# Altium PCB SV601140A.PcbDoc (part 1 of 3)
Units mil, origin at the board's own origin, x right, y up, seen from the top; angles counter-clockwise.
Board outline 5208 x 5464 mil, 4 copper layers (Top Layer, MidLayer1, MidLayer2, Bottom Layer), stack 61.2 mil thick; 45 components, 23 nets, 134 pads, 62 vias.
Unrouted connection lines stored in the file: 1.
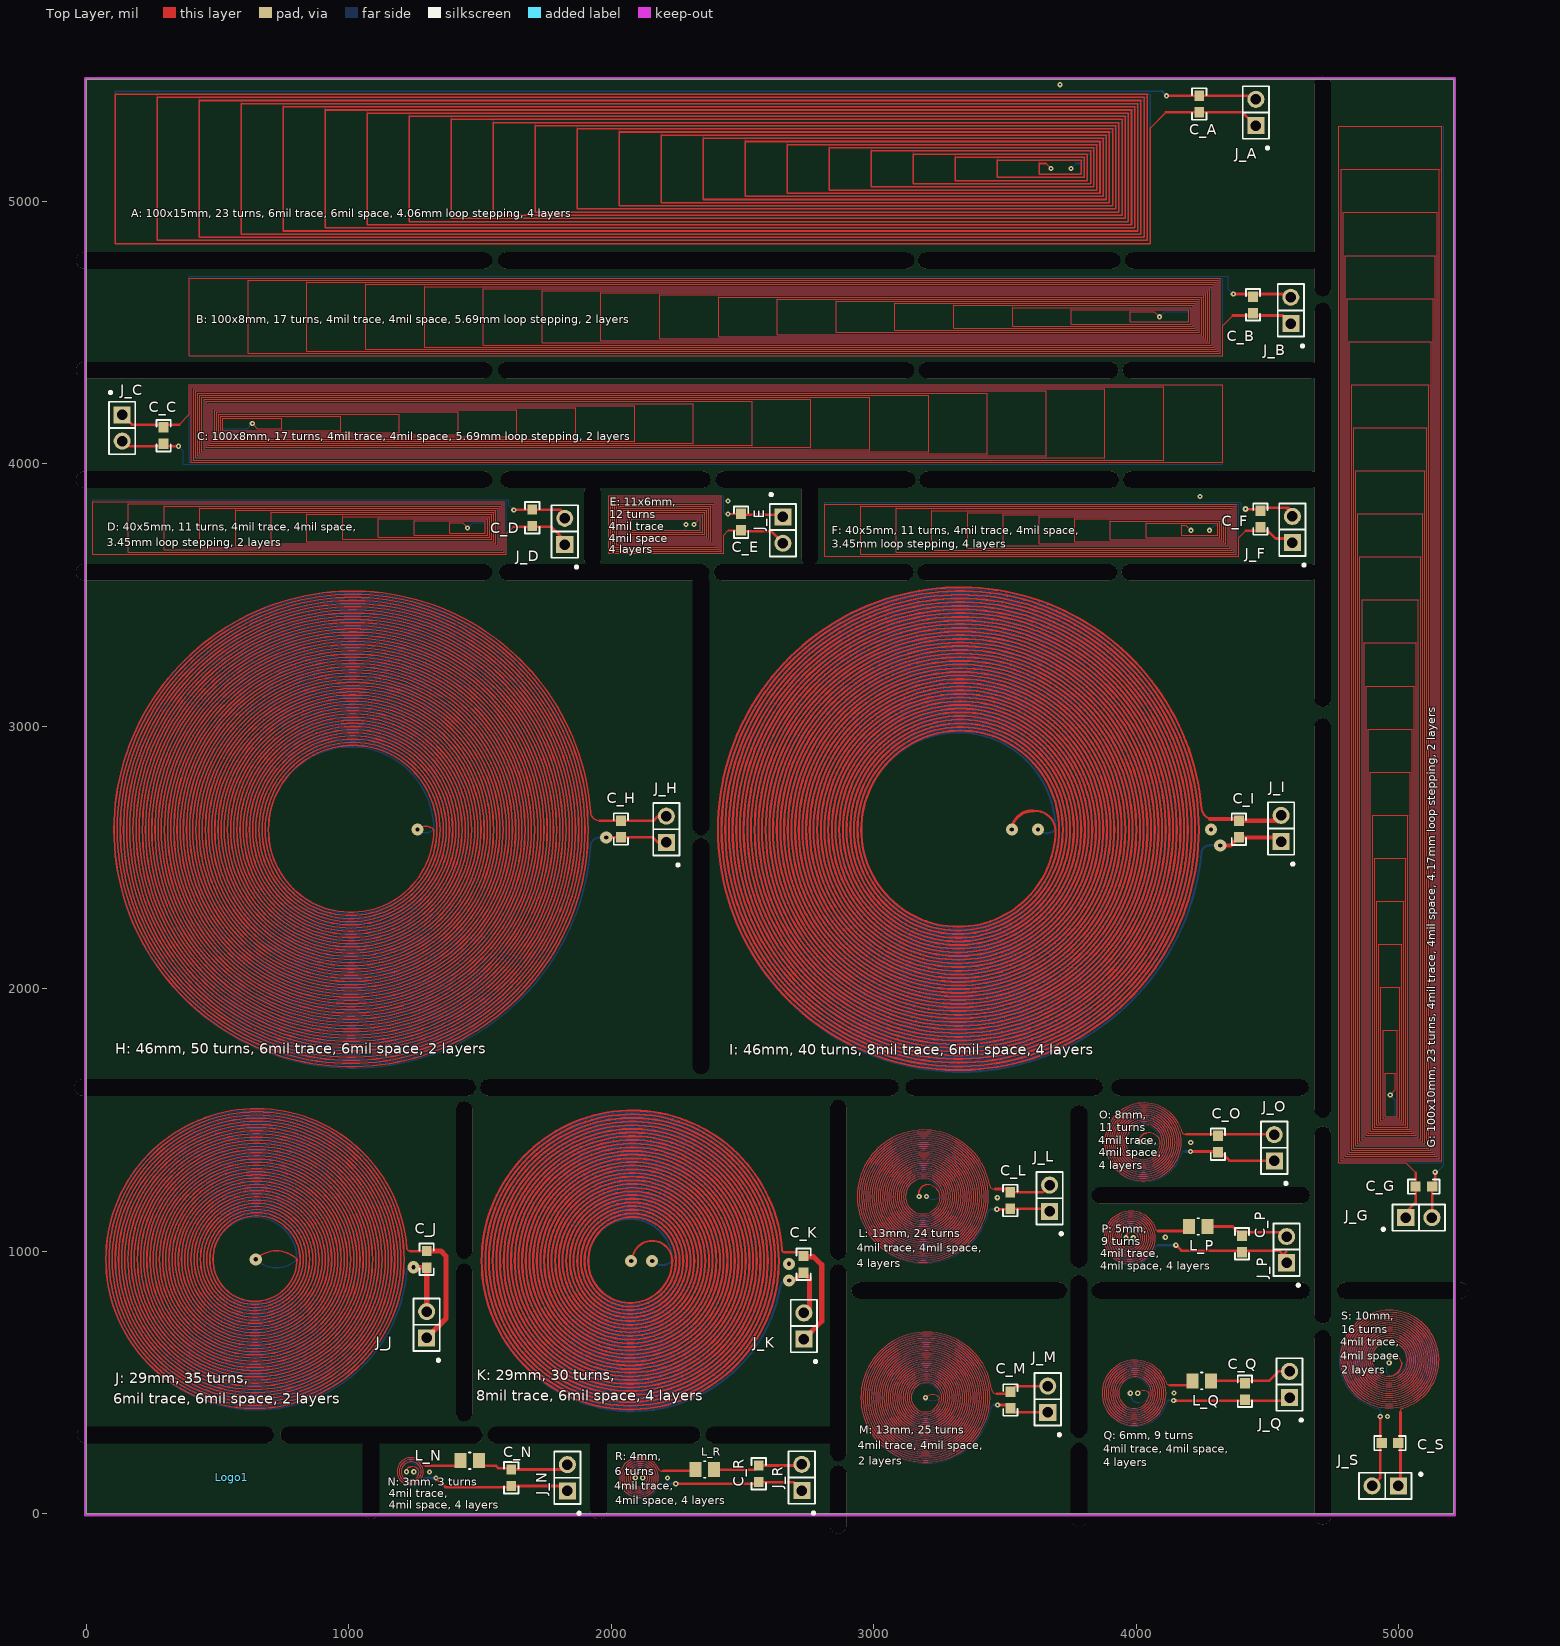
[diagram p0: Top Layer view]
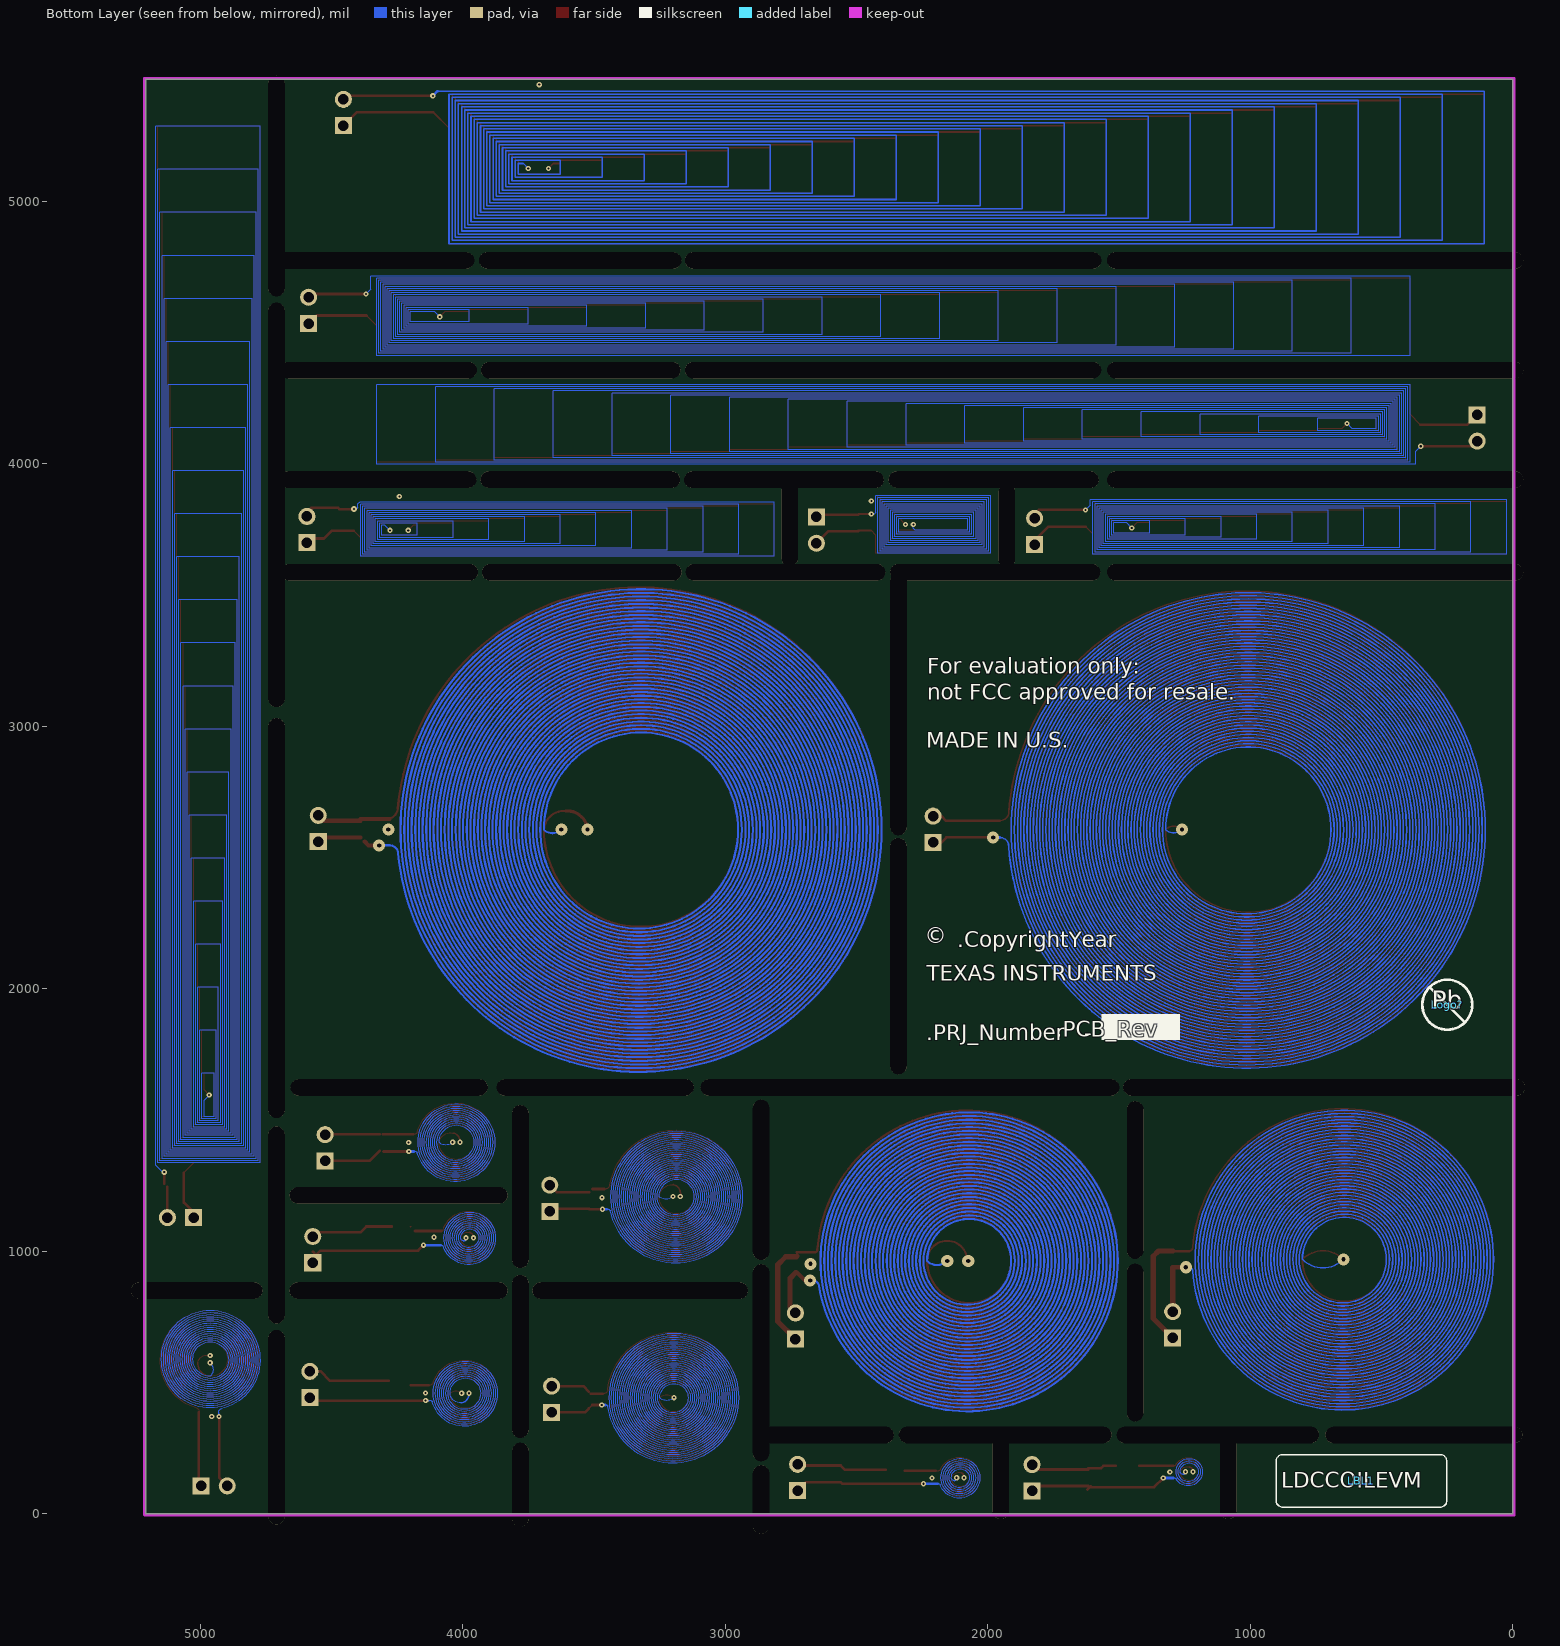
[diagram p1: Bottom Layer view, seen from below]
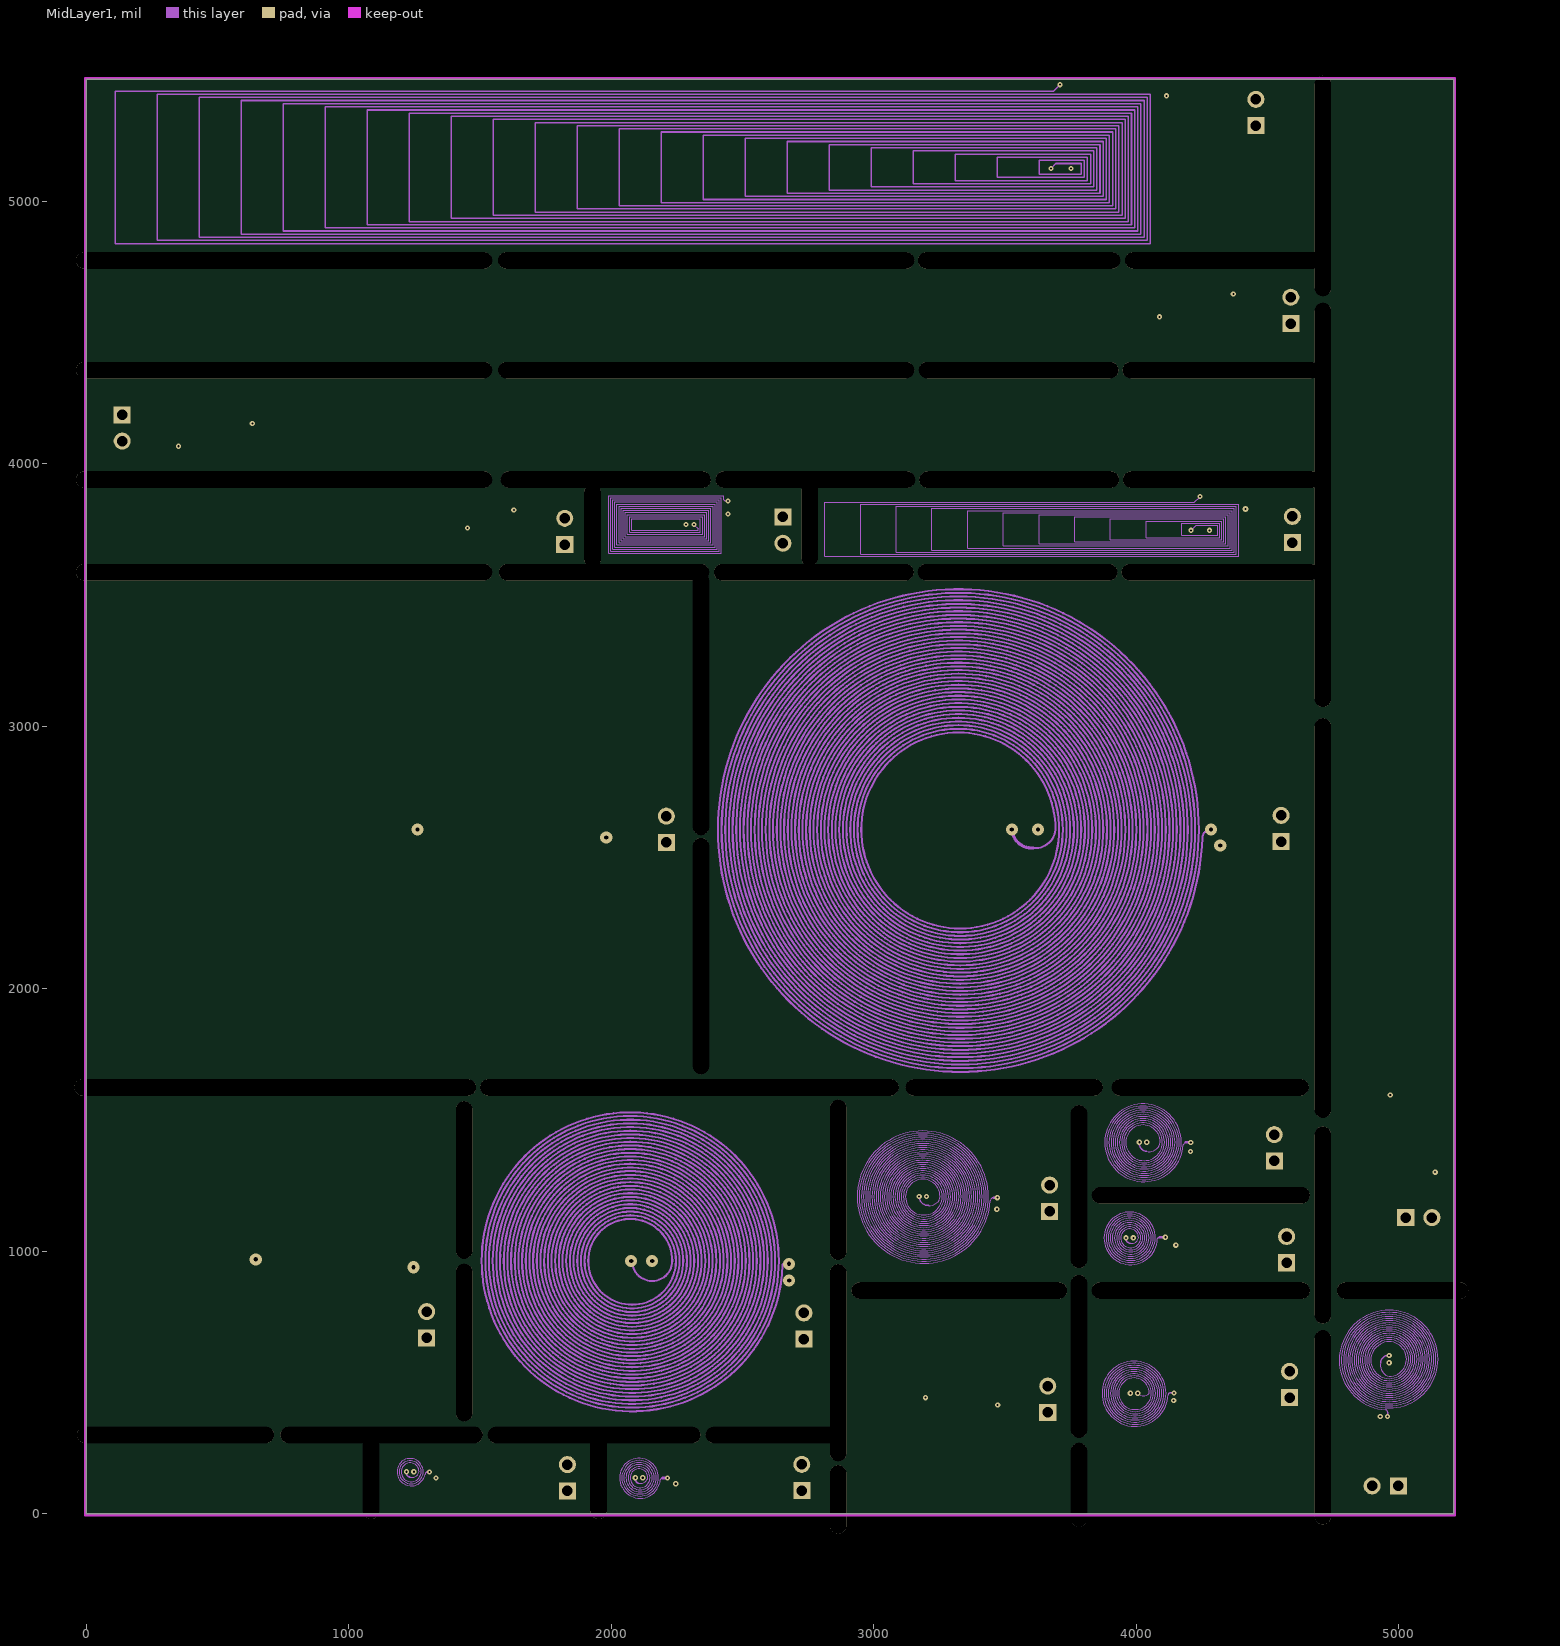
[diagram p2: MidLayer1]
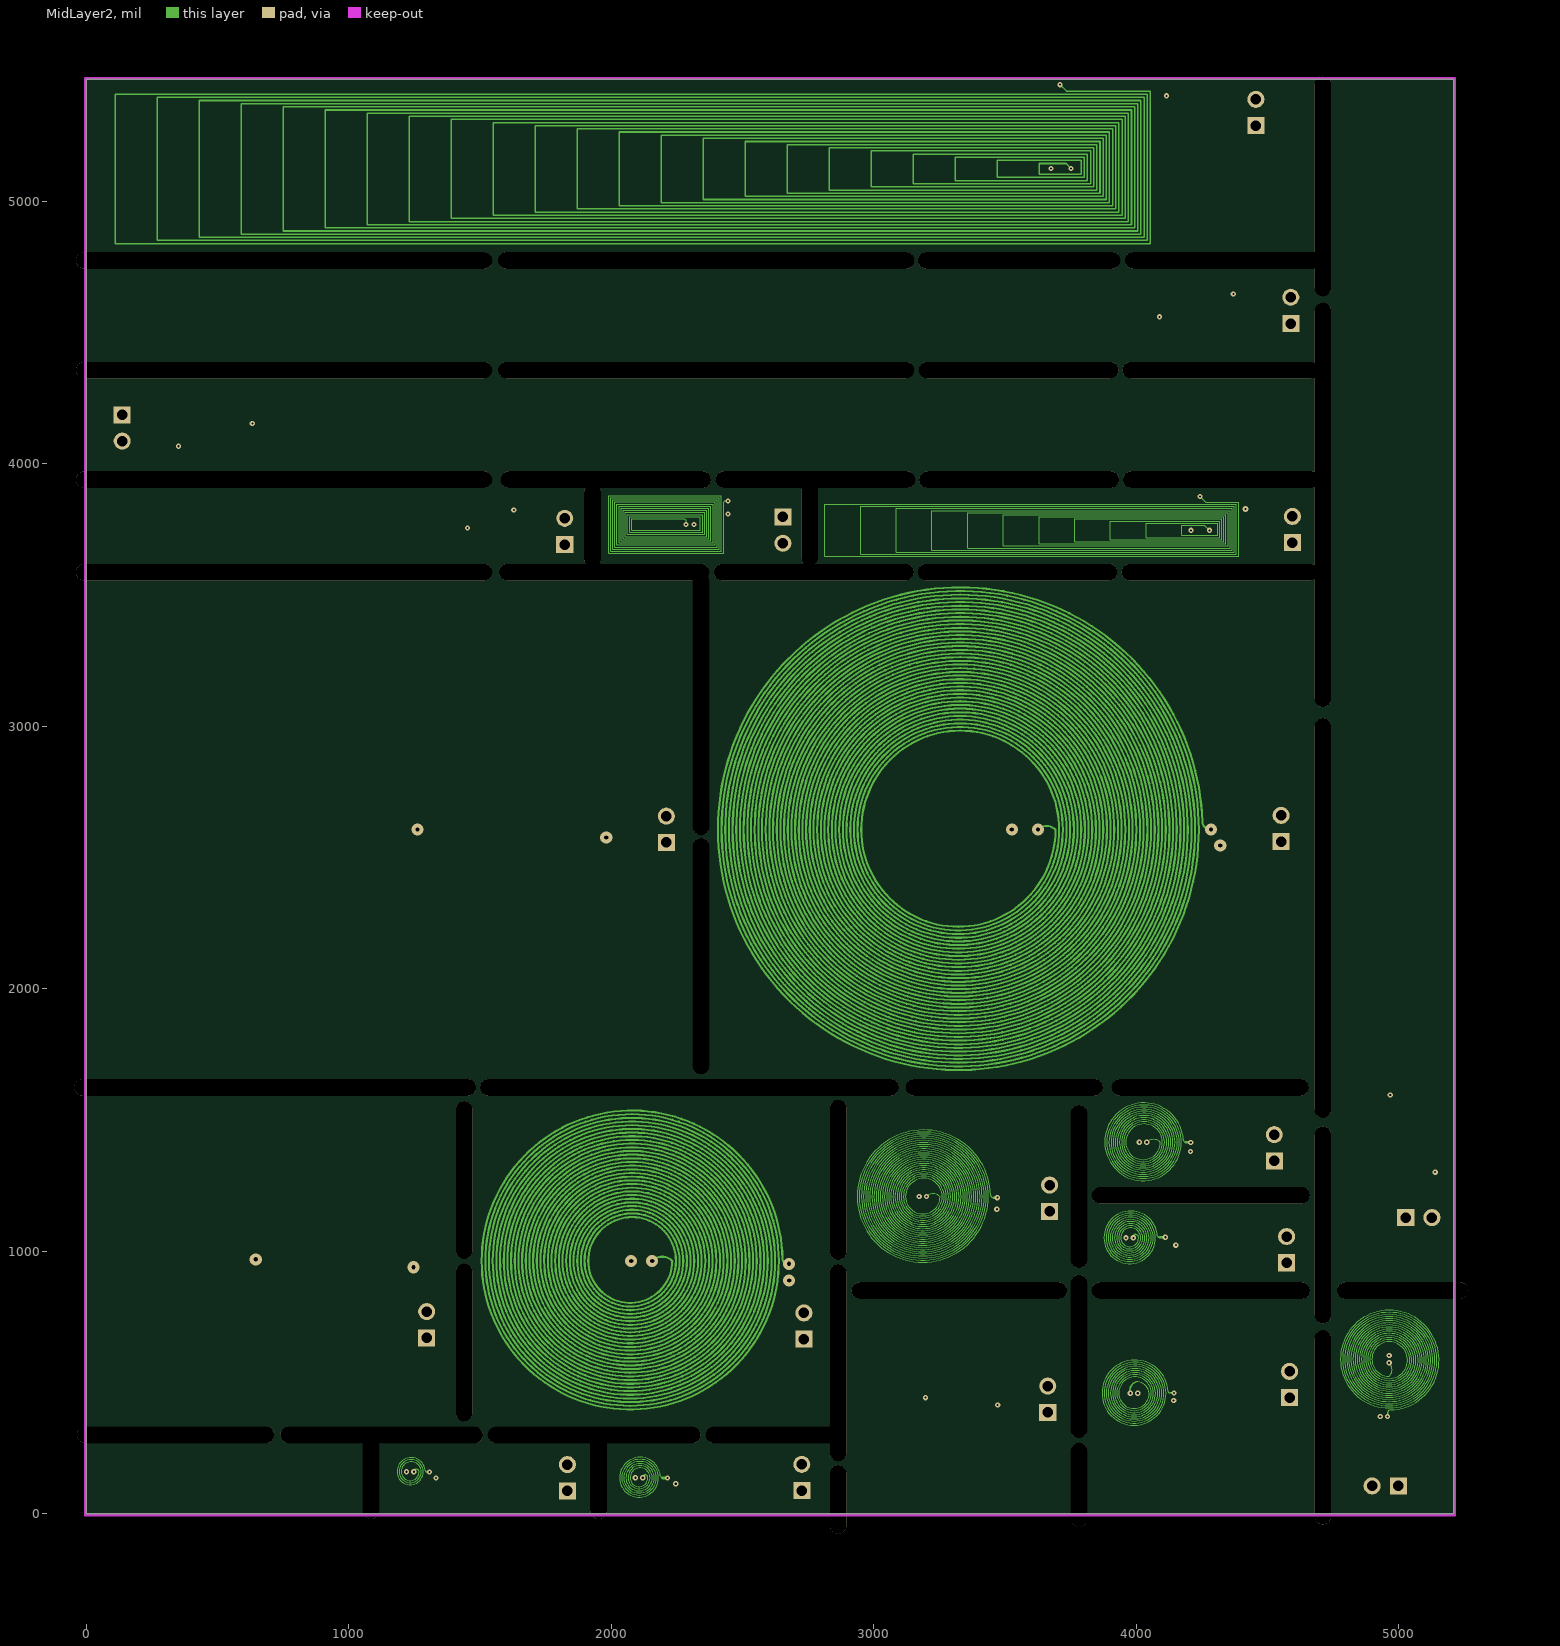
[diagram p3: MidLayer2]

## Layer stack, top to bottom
Top Solder: solder mask 0.4, Solder Resist, Dk 3.5
Top Layer: signal copper 1.4
Dielectric1: core 12.6, FR-4, Dk 3.9
MidLayer1: signal copper 1.4
Dielectric2: prepreg 30.4, FR-4, Dk 3.9
MidLayer2: signal copper 1.4
Dielectric3: core 12.6, FR-4, Dk 3.9
Bottom Layer: signal copper 1.4
Bottom Solder: solder mask 0.4, Solder Resist, Dk 3.5

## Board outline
0,0 0,5464 5208,5464 5208,0

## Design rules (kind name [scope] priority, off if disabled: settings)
AcuteAngle [All] p1: minimum=4.50000000000000E+0001 checktracksonly=FALSE
AssemblyTestPointUsage [All] p1: valid=2
Clearance Clearance_BoardEdge_MountingHoles [OnCopper and InComponentClass('Mounting Holes') vs IsKeepOut] p1: gap=40
Clearance Clearance_BoardEdge_Poly [OnCopper and InPoly vs IsKeepOut] p2: gap=25
Clearance Clearance_BoardEdge [OnCopper and Not InComponentClass('Logo') and not InComponentClass('FiducialMark') and not InRegion(1000,500,4000,800) and Not IsKeepout vs IsKeepOut] p3: gap=20
Clearance Clearance_Poly [InPolygon] p4: gap=25
Clearance [All] p5: gap=4
ComponentClearance ComponentClearance_Logo [InComponentClass('Logo')] p1: gap=50 collisioncheckmode=3 verticalgap=10 showdistances=FALSE
ComponentClearance ComponentClearance_ScrewToNut [(HasFootprint('NY PMS 440 0025 PH')) vs (HasFootprint('Keystone_1902C'))] p2: gap=5 collisioncheckmode=3 verticalgap=10 showdistances=FALSE
ComponentClearance ComponentClearance_MountingHoles [InComponentClass('Mounting Holes')] p3: gap=250 collisioncheckmode=3 verticalgap=100000 showdistances=FALSE
ComponentClearance ComponentClearance_SmallPassives [HasFootprint('0201*') or HasFootprint('0402*') or HasFootprint('0508') or HasFootprint('0603*') or HasFootprint('0612') or HasFootprint('0805*') or HasFootprint('0815*') or HasFootprint('0830*') or HasFootprint('1206*') or HasFootprint('1210*') or HasFootprint('1808*') or HasFootprint('1812*') or HasFootprint('1825*') or HasFootprint('2010*') or HasFootprint('2220*') or HasFootprint('2225*') or HasFootprint('2512*') or HasFootprint('2728*') or HasFootprint('3518*') vs HasFootprint('0201*') or HasFootprint('0402*') or HasFootprint('0508') or HasFootprint('0603*') or HasFootprint('0612') or HasFootprint('0805*') or HasFootprint('0815*') or HasFootprint('0830*') or HasFootprint('1206*') or HasFootprint('1210*') or HasFootprint('1808*') or HasFootprint('1812*') or HasFootprint('1825*') or HasFootprint('2010*') or HasFootprint('2220*') or HasFootprint('2225*') or HasFootprint('2512*') or HasFootprint('2728*') or HasFootprint('3518*')] p4: gap=20 collisioncheckmode=3 verticalgap=10 showdistances=FALSE
ComponentClearance ComponentClearance_THtoSMT [IsThruComponent vs IsSMTComponent] p5: gap=100 collisioncheckmode=3 verticalgap=30 showdistances=FALSE
ComponentClearance ComponentClearance_THtoTH [IsThruComponent vs IsThruComponent] p6: gap=118.11 collisioncheckmode=3 verticalgap=30 showdistances=FALSE
ComponentClearance [All] p7: gap=40 collisioncheckmode=3 verticalgap=10 showdistances=FALSE
DiffPairsRouting [All] p1: maxlimit=100 minlimit=10 mostfreqgap=10 toplayer_minwidth=15 toplayer_maxwidth=15 toplayer_prefwidth=15 midlayer1_minwidth=15 midlayer1_maxwidth=15 midlayer1_prefwidth=15 midlayer2_minwidth=15 midlayer2_maxwidth=15 midlayer2_prefwidth=15 bottomlayer_minwidth=15 bottomlayer_maxwidth=15 bottomlayer_prefwidth=15 maxuncoupledlength=1000
FabricationTestPointUsage TestPointUsage [All] p1: valid=2 allowmultiple=FALSE
FabricationTestpoint Testpoint [All] p1: side=3 testpointundercomponent=TRUE minsize=40 maxsize=100 preferedsize=60 minholesize=0 maxholesize=40 preferedholesize=32 testpointgrid=1 allowsidetop=TRUE allowsidebottom=TRUE usegrid=TRUE gridtolerance=0.01
FanoutControl Fanout_LCC [IsLCC] p1: bgadir=Out bgaviamode=Centered fanoutstyle=Auto fanoutdirection=Alternating viagrid=1 // Fanout_LCC (Default Rule)
FanoutControl Fanout_BGA [IsBGA] p2: bgadir=Out bgaviamode=Centered fanoutstyle=Auto fanoutdirection=Alternating viagrid=1 // Fanout_BGA (Default Rule)
FanoutControl Fanout_Default [All] p4: bgadir=Out bgaviamode=Centered fanoutstyle=Auto fanoutdirection=Alternating viagrid=1 // Fanout_Default (Default Rule)
FanoutControl Fanout_Small [(CompPinCount < 5)] p5: bgadir=Out bgaviamode=Centered fanoutstyle=Auto fanoutdirection=OutThenIn viagrid=1 // Fanout_Small (Default Rule)
HoleSize [All] p1: absolutevalues=TRUE maxlimit=251 minlimit=8 maxpercent=80.000 minpercent=20.000
MinimumAnnularRing MinimumAnnularRing_ThermalPadVias [IsVia and InAnyComponent] p1: minimumring=5.91
MinimumAnnularRing [All] p2: minimumring=6
MinimumSolderMaskSliver MinimumSolderMaskSliver_Logo [InComponentClass('Logo') vs InComponentClass('Logo')] p1: minsoldermaskwidth=0.7
MinimumSolderMaskSliver [All] p2: minsoldermaskwidth=3.94
PlaneConnect [All] p1: planeconnectstyle=Relief reliefexpansion=10 reliefentries=4 reliefconductorwidth=10 reliefairgap=10
PolygonConnect [All] p1: connectstyle=Relief reliefconductorwidth=10 reliefentries=4 polygonreliefangle="90 Angle" airgapwidth=10
RoutingVias ThermalPadVias [IsVia and InAnyComponent] p1: holewidth=7.87 width=19.68 viastyle="Through Hole" minholewidth=7.87 minwidth=19.68 maxholewidth=12.99 maxwidth=23.62
RoutingVias [All] p2: holewidth=16 width=34 viastyle="Through Hole" minholewidth=7.87 minwidth=20 maxholewidth=40 maxwidth=65
SMDToCorner [All] p1: distance=30000
SilkToSilkClearance [All] p1: silktosilkclearance=5
SilkToSolderMaskClearance SilkscreenOverComponentPads [IsPad] p1: minsilkscreentomaskgap=5 clearancetoexposedcopper=TRUE
SolderMaskExpansion [All] p1: expansion=1.97
UnpouredPolygon [All] p1: allowunpoured=FALSE
Width [All] p1: maxlimit=100 minlimit=4 preferedwidth=10 checkconnectedcopper=TRUE
15 further rules are at their usual default settings.

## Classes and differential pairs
component class Header: J_A J_B J_C J_D J_E J_F J_G J_H J_I J_J J_K J_L J_M J_N J_O J_P J_Q J_R J_S
component class Label: LBL1
component class Logo: Logo1

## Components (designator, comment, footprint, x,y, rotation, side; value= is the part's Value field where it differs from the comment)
C_A "06035A101FAT2A" 0603 4239,5370 r90 top
C_B "06035A101FAT2A" 0603 4444,4605 r90 top
C_C "06035A101FAT2A" 0603 294,4107 r90 top
C_D "06035A101FAT2A" 0603 1698,3794 r90 top
C_E "06035A101FAT2A" 0603 2494,3777.35 r270 top
C_F "06035A101FAT2A" 0603 4472,3789 r90 top
C_G "06035A101FAT2A" 0603 5094.7,1246 r0 top
C_H "06035A101FAT2A" 0603 2036,2608.3 r90 top
C_I "06035A101FAT2A" 0603 4390,2608 r270 top
C_J "06035A101FAT2A" 0603 1296,969 r90 top
C_K "06035A101FAT2A" 0603 2732,950 r90 top
C_L "06035A101FAT2A" 0603 3519,1193 r90 top
C_M "06035A101FAT2A" 0603 3520,433 r90 top
C_N "06035A101FAT2A" 0603 1618,137 r90 top
C_O "06035A101FAT2A" 0603 4310,1408 r90 top
C_P "06035A101FAT2A" 0603 4402,1028 r90 top
C_Q "06035A101FAT2A" 0603 4413,466 r90 top
C_R "06035A101FAT2A" 0603 2561,152 r90 top
C_S "06035A101FAT2A" 0603 4965.7,269 r0 top
J_A "TSW-102-07-G-S" TSW-102-07-G-S 4455,5338 r90 top
J_B "TSW-102-07-G-S" TSW-102-07-G-S 4588,4584 r90 top
J_C "TSW-102-07-G-S" TSW-102-07-G-S 136,4136 r270 top
J_D "TSW-102-07-G-S" TSW-102-07-G-S 1822,3742 r90 top
J_E "TSW-102-07-G-S" TSW-102-07-G-S 2653,3747 r270 top
J_F "TSW-102-07-G-S" TSW-102-07-G-S 4594,3749 r90 top
J_G "TSW-102-07-G-S" TSW-102-07-G-S 5075.7,1128 r0 top
J_H "TSW-102-07-G-S" TSW-102-07-G-S 2209,2607.3 r90 top
J_I "TSW-102-07-G-S" TSW-102-07-G-S 4551,2610.3 r90 top
J_J "TSW-102-07-G-S" TSW-102-07-G-S 1296,720 r90 top
J_K "TSW-102-07-G-S" TSW-102-07-G-S 2733,715 r90 top
J_L "TSW-102-07-G-S" TSW-102-07-G-S 3669,1202 r90 top
J_M "TSW-102-07-G-S" TSW-102-07-G-S 3662,436 r90 top
J_N "TSW-102-07-G-S" TSW-102-07-G-S 1832,137 r90 top
J_O "TSW-102-07-G-S" TSW-102-07-G-S 4525,1394 r90 top
J_P "TSW-102-07-G-S" TSW-102-07-G-S 4572,1006 r90 top
J_Q "TSW-102-07-G-S" TSW-102-07-G-S 4583,492 r90 top
J_R "TSW-102-07-G-S" TSW-102-07-G-S 2725,138 r90 top
J_S "TSW-102-07-G-S" TSW-102-07-G-S 4947.7,106 r180 top
L_N "MLZ2012N6R8LT000" 0805_145 1460,202 r180 top
L_P "MLZ2012N6R8LT000" 0805_145 4235,1094 r180 top
L_Q "MLZ2012N6R8LT000" 0805_145 4248.71,506 r180 top
L_R "MLZ2012N6R8LT000" 0805_145 2355,168 r180 top
LBL1 "Size: 0.65\" x 0.20 \"" Label_650x200 577,125 r180 bottom
Logo1 "Texas Instruments" TI_Stacked_SolderMask_Small 554,138 r0 top
Logo? "Pb-Free Symbol" Pb-Free_Overlay_Medium 250,1939 r180 bottom

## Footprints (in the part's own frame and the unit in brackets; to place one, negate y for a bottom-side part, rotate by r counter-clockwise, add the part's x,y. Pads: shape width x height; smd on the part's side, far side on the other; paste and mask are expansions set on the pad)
0603 [mm] "0603 from SM-752 data"
  rect 1x0.95 smd: 1(-0.8,0) 2(0.8,0)
  silkscreen extent -1.52,-0.69 1.52,0.69, body extent -0.87,-0.47 0.87,0.47, height 0.85
0805_145 [mm] "0805 / 1.45mm height"
  rect 1.15x1.45 smd: 1(-0.9,0) 2(0.9,0)
  silkscreen extent -0.1,-0.8 0.1,0.8, body extent -1.1,-0.72 1.1,0.72, height 1.45
Label_650x200 [mil] "Thermal Transfer Label"
  silkscreen extent -325,-100 325,100, body extent -326,-101 326,101, height 1
Pb-Free_Overlay_Medium [mil]
  silkscreen extent -95,-95 95,95
TI_Stacked_SolderMask_Small [mil]
  rect 900x250 on Top Paste paste-125 mask-125: 0(0,0)
TSW-102-07-G-S [mm] "Samtec 100mil, 1x2, 230 mil above insulator"
  rect 1.65x1.65 hole 1.016 mask+0: 1(-1.27,0)
  round 1.65 hole 1.016 mask+0: 2(1.27,0)
  silkscreen extent -3.56,-1.27 2.54,1.27, body extent -2.54,-1.27 2.54,1.27, height 8.38

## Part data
C_A C_B C_C C_D C_E C_F C_G C_H C_I C_J C_K C_L C_M C_N C_O C_P C_Q C_R C_S: library part GRM1885C2A300JA01D, "CAP CER 100PF 50V 1% NP0 0603"
J_A J_B J_C J_D J_E J_F J_G J_H J_I J_J J_K J_L J_M J_N J_O J_P J_Q J_R J_S: "Header, TH, 100mil, 2x1, Gold plated, 230 mil above insulator"
L_N L_P L_Q L_R: "Inductor, Multilayer, Ferrite, 6.8 µH, 0.11 A, 0.25 ohm, SMD"
LBL1: library part THT-14-423-10, "Thermal Transfer Printable Labels, 0.650\" W x 0.200\" H - 10,000 per roll"
Logo1: library part TI_Logo, "Texas Instrument Corporate Signature"
Logo?: library part Pb-Free

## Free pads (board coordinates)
  oval 750x62 hole 62 slot 750 at 0 deg unplated: 0(339,300) 0(3496,1624) 0(4281,1624) 0(4318,3586.35) 0(4322,4356.35) 0(4324,3939.35) 0(4332,4774.35)
  oval 1530x62 hole 62 slot 1530 at 0 deg unplated: 0(719,1624)
  oval 1585x62 hole 62 slot 1585 at 0 deg unplated: 0(753,3586.35) 0(753,3939.35) 0(753,4356.35) 0(753,4774.35) 0(2361,4356.35) 0(2361,4774.35)
  oval 62x320 hole 62 slot 320 at 90 deg unplated: 0(1084,140) 0(1928,3764) 0(1951,140) 0(2755,3769) 0(3781,110)
  oval 770x62 hole 62 slot 770 at 0 deg unplated: 0(1124,300) 0(3553,4774.35)
  oval 62x600 hole 62 slot 600 at 90 deg unplated: 0(1439,652) 0(1439,1271)
  oval 810x62 hole 62 slot 810 at 0 deg unplated: 0(1934,300)
  oval 800x62 hole 62 slot 800 at 0 deg unplated: 0(1972,3586.35) 0(1978,3939.35)
  oval 1594x62 hole 62 slot 1594 at 0 deg unplated: 0(2297,1624)
  oval 62x900 hole 62 slot 900 at 90 deg unplated: 0(2341,2124)
  oval 62x1000 hole 62 slot 1000 at 90 deg unplated: 0(2341,3085)
  oval 500x62 hole 62 slot 500 at 0 deg unplated: 0(2609,300) 0(5014,850)
  oval 760x62 hole 62 slot 760 at 0 deg unplated: 0(2771,3586.35) 0(2777,3939.35) 0(3547,3586.35) 0(3551,4356.35) 0(3553,3939.35)
  oval 62x260 hole 62 slot 260 at 90 deg unplated: 0(2864,54)
  oval 62x750 hole 62 slot 750 at 90 deg unplated: 0(2864,575) 0(4710,1100)
  oval 62x610 hole 62 slot 610 at 90 deg unplated: 0(2864,1272)
  oval 820x62 hole 62 slot 820 at 0 deg unplated: 0(3325,850)
  oval 62x620 hole 62 slot 620 at 90 deg unplated: 0(3781,599) 0(3781,1246)
  oval 830x62 hole 62 slot 830 at 0 deg unplated: 0(4245,850) 0(4245,1213)
  oval 62x740 hole 62 slot 740 at 90 deg unplated: 0(4710,329)
  oval 62x1522 hole 62 slot 1522 at 90 deg unplated: 0(4710,2269)
  oval 62x840 hole 62 slot 840 at 90 deg unplated: 0(4710,5058)
  oval 62x1540 hole 62 slot 1540 at 90 deg unplated: 0(4710,3843)

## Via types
v1: diameter 20, hole 8, Top Layer to Bottom Layer, tented both sides, 49 vias
v2: diameter 46, hole 16, Top Layer to Bottom Layer, tented both sides, 12 vias
v3: diameter 23, hole 8, Top Layer to Bottom Layer, tented both sides, 1 vias

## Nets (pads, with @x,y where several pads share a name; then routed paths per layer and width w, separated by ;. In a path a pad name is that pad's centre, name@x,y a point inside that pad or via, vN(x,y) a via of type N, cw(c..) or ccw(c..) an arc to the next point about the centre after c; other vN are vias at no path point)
NetC_A_1: C_A.1 C_A.2 J_A.1 J_A.2 | length 435565.1
  Top Layer w6: v1(3674,5125) 3655.5,5143.5 3629,5143.5 3629,5102.5 3789,5102.5 3789,5155.5 3469,5155.5 3469,5090.5 3801,5090.5 3801,5167.5 3309,5167.5 3309,5078.5 3813,5078.5 3813,5179.5 3149,5179.5 3149,5066.5 3825,5066.5 3825,5191.5 2989,5191.5 2989,5054.5 3837,5054.5 3837,5203.5 2829,5203.5 2829,5042.5 3849,5042.5 3849,5215.5 2669,5215.5 2669,5030.5 3861,5030.5 3861,5227.5 2509,5227.5 2509,5018.5 3873,5018.5 3873,5239.5 2349,5239.5 2349,5006.5 3885,5006.5 3885,5251.5 2189,5251.5 2189,4994.5 3897,4994.5 3897,5263.5 2029,5263.5 2029,4982.5 3909,4982.5 3909,5275.5 1869,5275.5 1869,4970.5 3921,4970.5 3921,5287.5 1709,5287.5 1709,4958.5 3933,4958.5 3933,5299.5 1549,5299.5 1549,4946.5 3945,4946.5 3945,5311.5 1389,5311.5 1389,4934.5 3957,4934.5 3957,5323.5 1229,5323.5 1229,4922.5 3969,4922.5 3969,5335.5 1069,5335.5 1069,4910.5 3981,4910.5 3981,5347.5 909,5347.5 909,4898.5 3993,4898.5 3993,5359.5 749,5359.5 749,4886.5 4005,4886.5 4005,5371.5 589,5371.5 589,4874.5 4017,4874.5 4017,5383.5 429,5383.5 429,4862.5 4029,4862.5 4029,5395.5 269,5395.5 269,4850.5 4041,4850.5 4041,5407.5 109,5407.5 109,4838.5 4053,4838.5 4053,5279 4112.5,5338.5
  Top Layer w10: 4112.5,5338.5 4404.5,5338.5 J_A.1@4455,5288 ; v1(4114.5,5401.5) 4441.5,5401.5 J_A.2@4455,5388
  MidLayer1 w6: v1(3674,5125) 3692.5,5143.5 3789,5143.5 3789,5102.5 3629,5102.5 3629,5155.5 3801,5155.5 3801,5090.5 3469,5090.5 3469,5167.5 3813,5167.5 3813,5078.5 3309,5078.5 3309,5179.5 3825,5179.5 3825,5066.5 3149,5066.5 3149,5191.5 3837,5191.5 3837,5054.5 2989,5054.5 2989,5203.5 3849,5203.5 3849,5042.5 2829,5042.5 2829,5215.5 3861,5215.5 3861,5030.5 2669,5030.5 2669,5227.5 3873,5227.5 3873,5018.5 2509,5018.5 2509,5239.5 3885,5239.5 3885,5006.5 2349,5006.5 2349,5251.5 3897,5251.5 3897,4994.5 2189,4994.5 2189,5263.5 3909,5263.5 3909,4982.5 2029,4982.5 2029,5275.5 3921,5275.5 3921,4970.5 1869,4970.5 1869,5287.5 3933,5287.5 3933,4958.5 1709,4958.5 1709,5299.5 3945,5299.5 3945,4946.5 1549,4946.5 1549,5311.5 3957,5311.5 3957,4934.5 1389,4934.5 1389,5323.5 3969,5323.5 3969,4922.5 1229,4922.5 1229,5335.5 3981,5335.5 3981,4910.5 1069,4910.5 1069,5347.5 3993,5347.5 3993,4898.5 909,4898.5 909,5359.5 4005,5359.5 4005,4886.5 749,4886.5 749,5371.5 4017,5371.5 4017,4874.5 589,4874.5 589,5383.5 4029,5383.5 4029,4862.5 429,4862.5 429,5395.5 4041,5395.5 4041,4850.5 269,4850.5 269,5407.5 4053,5407.5 4053,4838.5 109,4838.5 109,5419.5 3684.5,5419.5 v1(3709,5444)
  MidLayer2 w6: v1(3709,5444) 3733.5,5419.5 4053,5419.5 4053,4838.5 109,4838.5 109,5407.5 4041,5407.5 4041,4850.5 269,4850.5 269,5395.5 4029,5395.5 4029,4862.5 429,4862.5 429,5383.5 4017,5383.5 4017,4874.5 589,4874.5 589,5371.5 4005,5371.5 4005,4886.5 749,4886.5 749,5359.5 3993,5359.5 3993,4898.5 909,4898.5 909,5347.5 3981,5347.5 3981,4910.5 1069,4910.5 1069,5335.5 3969,5335.5 3969,4922.5 1229,4922.5 1229,5323.5 3957,5323.5 3957,4934.5 1389,4934.5 1389,5311.5 3945,5311.5 3945,4946.5 1549,4946.5 1549,5299.5 3933,5299.5 3933,4958.5 1709,4958.5 1709,5287.5 3921,5287.5 3921,4970.5 1869,4970.5 1869,5275.5 3909,5275.5 3909,4982.5 2029,4982.5 2029,5263.5 3897,5263.5 3897,4994.5 2189,4994.5 2189,5251.5 3885,5251.5 3885,5006.5 2349,5006.5 2349,5239.5 3873,5239.5 3873,5018.5 2509,5018.5 2509,5227.5 3861,5227.5 3861,5030.5 2669,5030.5 2669,5215.5 3849,5215.5 3849,5042.5 2829,5042.5 2829,5203.5 3837,5203.5 3837,5054.5 2989,5054.5 2989,5191.5 3825,5191.5 3825,5066.5 3149,5066.5 3149,5179.5 3813,5179.5 3813,5078.5 3309,5078.5 3309,5167.5 3801,5167.5 3801,5090.5 3469,5090.5 3469,5155.5 3789,5155.5 3789,5102.5 3629,5102.5 3629,5143.5 3732.5,5143.5 v1(3751,5125)
  Bottom Layer w6: v1(3751,5125) 3769.5,5143.5 3789,5143.5 3789,5102.5 3629,5102.5 3629,5155.5 3801,5155.5 3801,5090.5 3469,5090.5 3469,5167.5 3813,5167.5 3813,5078.5 3309,5078.5 3309,5179.5 3825,5179.5 3825,5066.5 3149,5066.5 3149,5191.5 3837,5191.5 3837,5054.5 2989,5054.5 2989,5203.5 3849,5203.5 3849,5042.5 2829,5042.5 2829,5215.5 3861,5215.5 3861,5030.5 2669,5030.5 2669,5227.5 3873,5227.5 3873,5018.5 2509,5018.5 2509,5239.5 3885,5239.5 3885,5006.5 2349,5006.5 2349,5251.5 3897,5251.5 3897,4994.5 2189,4994.5 2189,5263.5 3909,5263.5 3909,4982.5 2029,4982.5 2029,5275.5 3921,5275.5 3921,4970.5 1869,4970.5 1869,5287.5 3933,5287.5 3933,4958.5 1709,4958.5 1709,5299.5 3945,5299.5 3945,4946.5 1549,4946.5 1549,5311.5 3957,5311.5 3957,4934.5 1389,4934.5 1389,5323.5 3969,5323.5 3969,4922.5 1229,4922.5 1229,5335.5 3981,5335.5 3981,4910.5 1069,4910.5 1069,5347.5 3993,5347.5 3993,4898.5 909,4898.5 909,5359.5 4005,5359.5 4005,4886.5 749,4886.5 749,5371.5 4017,5371.5 4017,4874.5 589,4874.5 589,5383.5 4029,5383.5 4029,4862.5 429,4862.5 429,5395.5 4041,5395.5 4041,4850.5 269,4850.5 269,5407.5 4053,5407.5 4053,4838.5 109,4838.5 109,5419.5 4096.49,5419.5
  Bottom Layer w10: 4096.49,5419.5 v1(4114.5,5401.5)
NetC_B_1: C_B.1 C_B.2 J_B.1 J_B.2 | length 153506.3
  Top Layer w4: v1(4088,4559.5) 4068.5,4579 3976,4579 3976,4540 4200,4540 4200,4587 3752,4587 3752,4532 4208,4532 4208,4595 3528,4595 3528,4524 4216,4524 4216,4603 3304,4603 3304,4516 4224,4516 4224,4611 3080,4611 3080,4508 4232,4508 4232,4619 2856,4619 2856,4500 4240,4500 4240,4627 2632,4627 2632,4492 4248,4492 4248,4635 2408,4635 2408,4484 4256,4484 4256,4643 2184,4643 2184,4476 4264,4476 4264,4651 1960,4651 1960,4468 4272,4468 4272,4659 1736,4659 1736,4460 4280,4460 4280,4667 1512,4667 1512,4452 4288,4452 4288,4675 1288,4675 1288,4444 4296,4444 4296,4683 1064,4683 1064,4436 4304,4436 4304,4691 840,4691 840,4428 4312,4428 4312,4699 616,4699 616,4420 4320,4420 4320,4707 392,4707 392,4412 4328,4412 4328,4525.5 4367,4564.5
  Top Layer w10: 4367,4564.5 4557.5,4564.5 J_B.1@4588,4534 ; v1(4369,4646.5) 4575.5,4646.5 J_B.2@4588,4634
  Bottom Layer w4: v1(4088,4559.5) 4107.5,4579 4200,4579 4200,4540 3976,4540 3976,4587 4208,4587 4208,4532 3752,4532 3752,4595 4216,4595 4216,4524 3528,4524 3528,4603 4224,4603 4224,4516 3304,4516 3304,4611 4232,4611 4232,4508 3080,4508 3080,4619 4240,4619 4240,4500 2856,4500 2856,4627 4248,4627 4248,4492 2632,4492 2632,4635 4256,4635 4256,4484 2408,4484 2408,4643 4264,4643 4264,4476 2184,4476 2184,4651 4272,4651 4272,4468 1960,4468 1960,4659 4280,4659 4280,4460 1736,4460 1736,4667 4288,4667 4288,4452 1512,4452 1512,4675 4296,4675 4296,4444 1288,4444 1288,4683 4304,4683 4304,4436 1064,4436 1064,4691 4312,4691 4312,4428 840,4428 840,4699 4320,4699 4320,4420 616,4420 616,4707 4328,4707 4328,4412 392,4412 392,4715 4350.5,4715 4350.5,4665 v1(4369,4646.5)
NetC_C_1: C_C.1 C_C.2 J_C.1 J_C.2 | length 153504.1
  Top Layer w4: 353,4148.5 392,4187.5 392,4301 4328,4301 4328,4006 400,4006 400,4293 4104,4293 4104,4014 408,4014 408,4285 3880,4285 3880,4022 416,4022 416,4277 3656,4277 3656,4030 424,4030 424,4269 3432,4269 3432,4038 432,4038 432,4261 3208,4261 3208,4046 440,4046 440,4253 2984,4253 2984,4054 448,4054 448,4245 2760,4245 2760,4062 456,4062 456,4237 2536,4237 2536,4070 464,4070 464,4229 2312,4229 2312,4078 472,4078 472,4221 2088,4221 2088,4086 480,4086 480,4213 1864,4213 1864,4094 488,4094 488,4205 1640,4205 1640,4102 496,4102 496,4197 1416,4197 1416,4110 504,4110 504,4189 1192,4189 1192,4118 512,4118 512,4181 968,4181 968,4126 520,4126 520,4173 744,4173 744,4134 651.5,4134 v1(632,4153.5)
  Top Layer w10: J_C.2@136,4086 155.5,4066.5 v1(351,4066.5) ; J_C.1@136,4186 173.5,4148.5 353,4148.5
  Bottom Layer w4: v1(351,4066.5) 369.5,4048 369.5,3998 4328,3998 4328,4301 392,4301 392,4006 4104,4006 4104,4293 400,4293 400,4014 3880,4014 3880,4285 408,4285 408,4022 3656,4022 3656,4277 416,4277 416,4030 3432,4030 3432,4269 424,4269 424,4038 3208,4038 3208,4261 432,4261 432,4046 2984,4046 2984,4253 440,4253 440,4054 2760,4054 2760,4245 448,4245 448,4062 2536,4062 2536,4237 456,4237 456,4070 2312,4070 2312,4229 464,4229 464,4078 2088,4078 2088,4221 472,4221 472,4086 1864,4086 1864,4213 480,4213 480,4094 1640,4094 1640,4205 488,4205 488,4102 1416,4102 1416,4197 496,4197 496,4110 1192,4110 1192,4189 504,4189 504,4118 968,4118 968,4181 512,4181 512,4126 744,4126 744,4173 520,4173 520,4134 612.5,4134 v1(632,4153.5)
NetC_D_1: C_D.1 C_D.2 J_D.1 J_D.2 pad.0@753,3586.35 | length 43473.8
  Top Layer w4: v1(1452,3755) 1432.5,3774.5 1384,3774.5 1384,3735.5 1520,3735.5 1520,3782.5 1248,3782.5 1248,3727.5 1528,3727.5 1528,3790.5 1112,3790.5 1112,3719.5 1536,3719.5 1536,3798.5 976,3798.5 976,3711.5 1544,3711.5 1544,3806.5 840,3806.5 840,3703.5 1552,3703.5 1552,3814.5 704,3814.5 704,3695.5 1560,3695.5 1560,3822.5 568,3822.5 568,3687.5 1568,3687.5 1568,3830.5 432,3830.5 432,3679.5 1576,3679.5 1576,3838.5 296,3838.5 296,3671.5 1584,3671.5 1584,3846.5 160,3846.5 160,3663.5 1592,3663.5 1592,3854.5 24,3854.5 24,3655.5 1600,3655.5 1600,3732.5 1628,3760.5
  Top Layer w10: 1628,3760.5 1769.5,3760.5 J_D.1@1822,3708 ; v1(1628,3824) 1806,3824 J_D.2@1822,3808
  Bottom Layer w4: v1(1452,3755) 1471.5,3774.5 1520,3774.5 1520,3735.5 1384,3735.5 1384,3782.5 1528,3782.5 1528,3727.5 1248,3727.5 1248,3790.5 1536,3790.5 1536,3719.5 1112,3719.5 1112,3798.5 1544,3798.5 1544,3711.5 976,3711.5 976,3806.5 1552,3806.5 1552,3703.5 840,3703.5 840,3814.5 1560,3814.5 1560,3695.5 704,3695.5 704,3822.5 1568,3822.5 1568,3687.5 568,3687.5 568,3830.5 1576,3830.5 1576,3679.5 432,3679.5 432,3838.5 1584,3838.5 1584,3671.5 296,3671.5 296,3846.5 1592,3846.5 1592,3663.5 160,3663.5 160,3854.5 1600,3854.5 1600,3655.5 24,3655.5 24,3862.5 1609.5,3862.5 1609.5,3842.5 v1(1628,3824)
NetC_E_1: C_E.1 C_E.2 J_E.1 J_E.2 | length 46225.6
  Top Layer w4: v1(2314,3768.35) 2331,3785.35 2331,3790.35 2077,3790.35 2077,3746.35 2339,3746.35 2339,3798.35 2069,3798.35 2069,3738.35 2347,3738.35 2347,3806.35 2061,3806.35 2061,3730.35 2355,3730.35 2355,3814.35 2053,3814.35 2053,3722.35 2363,3722.35 2363,3822.35 2045,3822.35 2045,3714.35 2371,3714.35 2371,3830.35 2037,3830.35 2037,3706.35 2379,3706.35 2379,3838.35 2029,3838.35 2029,3698.35 2387,3698.35 2387,3846.35 2021,3846.35 2021,3690.35 2395,3690.35 2395,3854.35 2013,3854.35 2013,3682.35 2403,3682.35 2403,3862.35 2005,3862.35 2005,3674.35 2411,3674.35 2411,3870.35 1997,3870.35 1997,3666.35 2419,3666.35 2419,3878.35 1989,3878.35 1989,3658.35 2427,3658.35 2427,3727.67 2445.18,3745.85
  Top Layer w8: v1(2444,3808.35) C_E.1@2493.5,3808.35 ; 2445.18,3745.85 C_E.2@2494,3745.85
  Top Layer w10: C_E.2@2494,3743.18 2606.82,3743.18 J_E.2@2653,3697 ; C_E.1@2494,3806.17 2643.83,3806.17 J_E.1@2653,3797
  MidLayer1 w4: v1(2314,3768.35) 2331,3751.35 2331,3746.35 2077,3746.35 2077,3790.35 2339,3790.35 2339,3738.35 2069,3738.35 2069,3798.35 2347,3798.35 2347,3730.35 2061,3730.35 2061,3806.35 2355,3806.35 2355,3722.35 2053,3722.35 2053,3814.35 2363,3814.35 2363,3714.35 2045,3714.35 2045,3822.35 2371,3822.35 2371,3706.35 2037,3706.35 2037,3830.35 2379,3830.35 2379,3698.35 2029,3698.35 2029,3838.35 2387,3838.35 2387,3690.35 2021,3690.35 2021,3846.35 2395,3846.35 2395,3682.35 2013,3682.35 2013,3854.35 2403,3854.35 2403,3674.35 2005,3674.35 2005,3862.35 2411,3862.35 2411,3666.35 1997,3666.35 1997,3870.35 2419,3870.35 2419,3658.35 1989,3658.35 1989,3878.35 2427,3878.35 2427,3863.35 2432,3858.35 v1(2444,3858.35)
  MidLayer2 w4: v1(2284,3768.35) 2284,3783.67 2277.33,3790.35 2077,3790.35 2077,3746.35 2339,3746.35 2339,3798.35 2069,3798.35 2069,3738.35 2347,3738.35 2347,3806.35 2061,3806.35 2061,3730.35 2355,3730.35 2355,3814.35 2053,3814.35 2053,3722.35 2363,3722.35 2363,3822.35 2045,3822.35 2045,3714.35 2371,3714.35 2371,3830.35 2037,3830.35 2037,3706.35 2379,3706.35 2379,3838.35 2029,3838.35 2029,3698.35 2387,3698.35 2387,3846.35 2021,3846.35 2021,3690.35 2395,3690.35 2395,3854.35 2013,3854.35 2013,3682.35 2403,3682.35 2403,3862.35 2005,3862.35 2005,3674.35 2411,3674.35 2411,3870.35 1997,3870.35 1997,3666.35 2419,3666.35 2419,3878.35 1989,3878.35 1989,3658.35 2427,3658.35 2427,3853.35 2432,3858.35 v1(2444,3858.35)
  Bottom Layer w4: v1(2284,3768.35) 2284,3753.67 2276.67,3746.35 2077,3746.35 2077,3790.35 2339,3790.35 2339,3738.35 2069,3738.35 2069,3798.35 2347,3798.35 2347,3730.35 2061,3730.35 2061,3806.35 2355,3806.35 2355,3722.35 2053,3722.35 2053,3814.35 2363,3814.35 2363,3714.35 2045,3714.35 2045,3822.35 2371,3822.35 2371,3706.35 2037,3706.35 2037,3830.35 2379,3830.35 2379,3698.35 2029,3698.35 2029,3838.35 2387,3838.35 2387,3690.35 2021,3690.35 2021,3846.35 2395,3846.35 2395,3682.35 2013,3682.35 2013,3854.35 2403,3854.35 2403,3674.35 2005,3674.35 2005,3862.35 2411,3862.35 2411,3666.35 1997,3666.35 1997,3870.35 2419,3870.35 2419,3658.35 1989,3658.35 1989,3878.35 2427,3878.35 2427,3814.67 2433.33,3808.35 v1(2444,3808.35)
NetC_F_1: C_F.1 C_F.2 J_F.1 J_F.2 | length 86543.7
  Top Layer w4: v1(4208,3746) 4188.5,3765.5 4173,3765.5 4173,3726.5 4309,3726.5 4309,3773.5 4037,3773.5 4037,3718.5 4317,3718.5 4317,3781.5 3901,3781.5 3901,3710.5 4325,3710.5 4325,3789.5 3765,3789.5 3765,3702.5 4333,3702.5 4333,3797.5 3629,3797.5 3629,3694.5 4341,3694.5 4341,3805.5 3493,3805.5 3493,3686.5 4349,3686.5 4349,3813.5 3357,3813.5 3357,3678.5 4357,3678.5 4357,3821.5 3221,3821.5 3221,3670.5 4365,3670.5 4365,3829.5 3085,3829.5 3085,3662.5 4373,3662.5 4373,3837.5 2949,3837.5 2949,3654.5 4381,3654.5 4381,3845.5 2813,3845.5 2813,3646.5 4389,3646.5 4389,3718 4416,3745
  Top Layer w10: v3(4415,3827) C_F.2@4471.5,3827 ; 4416,3745 4499.5,3745 4529.5,3715 J_F.1@4594,3715 ; C_F.2@4475,3832.5 4576.5,3832.5 J_F.2@4594,3815 ; 4571.5,3830.5 J_F.2@4586,3816
  MidLayer1 w4: v1(4208,3746) 4227.5,3765.5 4309,3765.5 4309,3726.5 4173,3726.5 4173,3773.5 4317,3773.5 4317,3718.5 4037,3718.5 4037,3781.5 4325,3781.5 4325,3710.5 3901,3710.5 3901,3789.5 4333,3789.5 4333,3702.5 3765,3702.5 3765,3797.5 4341,3797.5 4341,3694.5 3629,3694.5 3629,3805.5 4349,3805.5 4349,3686.5 3493,3686.5 3493,3813.5 4357,3813.5 4357,3678.5 3357,3678.5 3357,3821.5 4365,3821.5 4365,3670.5 3221,3670.5 3221,3829.5 4373,3829.5 4373,3662.5 3085,3662.5 3085,3837.5 4381,3837.5 4381,3654.5 2949,3654.5 2949,3845.5 4389,3845.5 4389,3646.5 2813,3646.5 2813,3853.5 4220.5,3853.5 v1(4242,3875)
  MidLayer2 w4: v1(4242,3875) 4263.5,3853.5 4389,3853.5 4389,3646.5 2813,3646.5 2813,3845.5 4381,3845.5 4381,3654.5 2949,3654.5 2949,3837.5 4373,3837.5 4373,3662.5 3085,3662.5 3085,3829.5 4365,3829.5 4365,3670.5 3221,3670.5 3221,3821.5 4357,3821.5 4357,3678.5 3357,3678.5 3357,3813.5 4349,3813.5 4349,3686.5 3493,3686.5 3493,3805.5 4341,3805.5 4341,3694.5 3629,3694.5 3629,3797.5 4333,3797.5 4333,3702.5 3765,3702.5 3765,3789.5 4325,3789.5 4325,3710.5 3901,3710.5 3901,3781.5 4317,3781.5 4317,3718.5 4037,3718.5 4037,3773.5 4309,3773.5 4309,3726.5 4173,3726.5 4173,3765.5 4258.5,3765.5 v1(4278,3746)
  Bottom Layer w4: v1(4278,3746) 4297.5,3765.5 4309,3765.5 4309,3726.5 4173,3726.5 4173,3773.5 4317,3773.5 4317,3718.5 4037,3718.5 4037,3781.5 4325,3781.5 4325,3710.5 3901,3710.5 3901,3789.5 4333,3789.5 4333,3702.5 3765,3702.5 3765,3797.5 4341,3797.5 4341,3694.5 3629,3694.5 3629,3805.5 4349,3805.5 4349,3686.5 3493,3686.5 3493,3813.5 4357,3813.5 4357,3678.5 3357,3678.5 3357,3821.5 4365,3821.5 4365,3670.5 3221,3670.5 3221,3829.5 4373,3829.5 4373,3662.5 3085,3662.5 3085,3837.5 4381,3837.5 4381,3654.5 2949,3654.5 2949,3845.5 4389,3845.5 4389,3646.5 2813,3646.5 2813,3853.5 4393.5,3853.5 4400,3847 4400,3833 4406,3827 v3(4415,3827)
NetC_G_1: C_G.1 C_G.2 J_G.1 J_G.2 | length 209636.8
  Top Layer w4: v1(4966.7,1595) 4986.2,1614.5 4986.2,1677 4947.2,1677 4947.2,1513 4994.2,1513 4994.2,1841 4939.2,1841 4939.2,1505 5002.2,1505 5002.2,2005 4931.2,2005 4931.2,1497 5010.2,1497 5010.2,2169 4923.2,2169 4923.2,1489 5018.2,1489 5018.2,2333 4915.2,2333 4915.2,1481 5026.2,1481 5026.2,2497 4907.2,2497 4907.2,1473 5034.2,1473 5034.2,2661 4899.2,2661 4899.2,1465 5042.2,1465 5042.2,2825 4891.2,2825 4891.2,1457 5050.2,1457 5050.2,2989 4883.2,2989 4883.2,1449 5058.2,1449 5058.2,3153 4875.2,3153 4875.2,1441 5066.2,1441 5066.2,3317 4867.2,3317 4867.2,1433 5074.2,1433 5074.2,3481 4859.2,3481 4859.2,1425 5082.2,1425 5082.2,3645 4851.2,3645 4851.2,1417 5090.2,1417 5090.2,3809 4843.2,3809 4843.2,1409 5098.2,1409 5098.2,3973 4835.2,3973 4835.2,1401 5106.2,1401 5106.2,4137 4827.2,4137 4827.2,1393 5114.2,1393 5114.2,4301 4819.2,4301 4819.2,1385 5122.2,1385 5122.2,4465 4811.2,4465 4811.2,1377 5130.2,1377 5130.2,4629 4803.2,4629 4803.2,1369 5138.2,1369 5138.2,4793 4795.2,4793 4795.2,1361 5146.2,1361 5146.2,4957 4787.2,4957 4787.2,1353 5154.2,1353 5154.2,5121 4779.2,5121 4779.2,1345 5162.2,1345 5162.2,5285 4771.2,5285 4771.2,1337 5025.71,1337 5063.2,1299.5
  Top Layer w10: J_G.1@5005.7,1128 5063.2,1185.5 C_G.1@5063.2,1246 5063.2,1299.5 ; J_G.2@5105.7,1128 5126.2,1148.5 C_G.2@5126.2,1246 ; C_G.2@5137.7,1257.5 v1(5137.7,1301)
  Bottom Layer w4: v1(4966.7,1595) 4986.2,1575.5 4986.2,1513 4947.2,1513 4947.2,1677 4994.2,1677 4994.2,1505 4939.2,1505 4939.2,1841 5002.2,1841 5002.2,1497 4931.2,1497 4931.2,2005 5010.2,2005 5010.2,1489 4923.2,1489 4923.2,2169 5018.2,2169 5018.2,1481 4915.2,1481 4915.2,2333 5026.2,2333 5026.2,1473 4907.2,1473 4907.2,2497 5034.2,2497 5034.2,1465 4899.2,1465 4899.2,2661 5042.2,2661 5042.2,1457 4891.2,1457 4891.2,2825 5050.2,2825 5050.2,1449 4883.2,1449 4883.2,2989 5058.2,2989 5058.2,1441 4875.2,1441 4875.2,3153 5066.2,3153 5066.2,1433 4867.2,1433 4867.2,3317 5074.2,3317 5074.2,1425 4859.2,1425 4859.2,3481 5082.2,3481 5082.2,1417 4851.2,1417 4851.2,3645 5090.2,3645 5090.2,1409 4843.2,1409 4843.2,3809 5098.2,3809 5098.2,1401 4835.2,1401 4835.2,3973 5106.2,3973 5106.2,1393 4827.2,1393 4827.2,4137 5114.2,4137 5114.2,1385 4819.2,1385 4819.2,4301 5122.2,4301 5122.2,1377 4811.2,1377 4811.2,4465 5130.2,4465 5130.2,1369 4803.2,1369 4803.2,4629 5138.2,4629 5138.2,1361 4795.2,1361 4795.2,4793 5146.2,4793 5146.2,1353 4787.2,1353 4787.2,4957 5154.2,4957 5154.2,1345 4779.2,1345 4779.2,5121 5162.2,5121 5162.2,1337 4771.2,1337 4771.2,5285 5170.2,5285 5170.2,1327 v1@5144.2,1301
